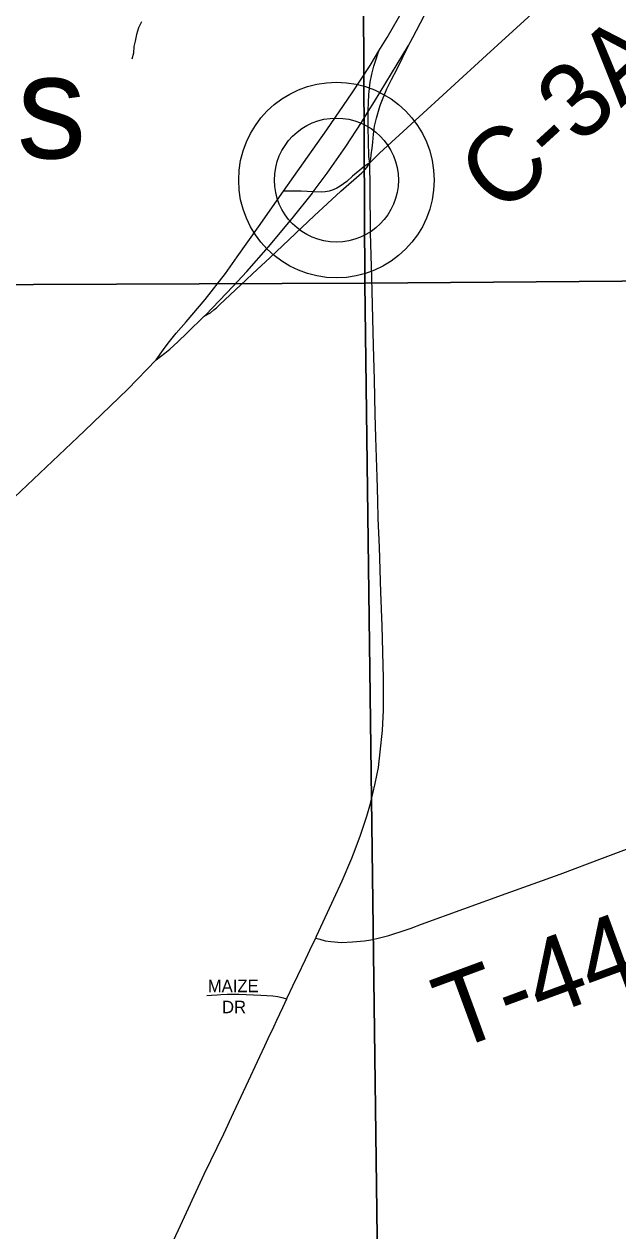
# Model space of a CAD drawing. Extents: x 1985906 to 2360102, y 891258 to 1222054.
# Drawn here: x 2113154 to 2115541, y 1005610 to 1010455 of the extents above; entities that cross this region are included whole.
import ezdxf

# ---------------------------------------------------------------- set-up
doc = ezdxf.new("R2010")
doc.units = 0
for name, color, linetype in [('GM_X_County_Road', 7, 'Continuous'), ('GM_X_County_Road_Text', 7, 'Continuous'), ('GM_X_Interchange_Ramps', 7, 'Continuous'), ('GM_X_Minor_River', 7, 'Continuous'), ('GM_X_Section', 7, 'Continuous'), ('GM_X_State_Route', 7, 'Continuous'), ('GM_X_Township_Road', 7, 'Continuous'), ('GM_X_Township_Road_Text', 7, 'Continuous'), ('GM_X_Township_Subdivision', 7, 'Continuous'), ('GM_X_Township_Subdivision_Text', 7, 'Continuous'), ('GM_X_Unincorporated', 7, 'Continuous'), ('GM_X_Unincorporated_Location', 7, 'Continuous'), ('GM_X_Unincorporated_Text', 7, 'Continuous')]:
    doc.layers.add(name, color=color, linetype=linetype)

msp = doc.modelspace()

# ---------------------------------------------------------------- linework, layer by layer
at = {"layer": 'GM_X_County_Road'}
msp.add_lwpolyline([(2114543.7, 1009898.7), (2114582.7, 1009937.4), (2115013.2, 1010331.1), (2115315.3, 1010608.1), (2115472.7, 1010751.8), (2115809.7, 1011062.8), (2115859.7, 1011112.8), (2115925.8, 1011178.1), (2116009.8, 1011269), (2116069.3, 1011335.5), (2116575.6, 1011894.5), (2116873, 1012222.5), (2116943.9, 1012300.3)], dxfattribs=at)
at = {"layer": 'GM_X_Interchange_Ramps'}
for points in [[(2113878.4, 1009282.4), (2113902.9, 1009296.1), (2113916.9, 1009307.5), (2113927.2, 1009316), (2113939.9, 1009327.8), (2114046.9, 1009428.3), (2114071.5, 1009453.2), (2114143.3, 1009518.7), (2114320.5, 1009685.1), (2114427.3, 1009784.6), (2114511.8, 1009858.8), (2114523.8, 1009870), (2114531.5, 1009880.1), (2114543.7, 1009898.7)], [(2114543.7, 1009898.7), (2114520.6, 1009883.3), (2114503, 1009868.6), (2114474.5, 1009845.3), (2114450.7, 1009823.7), (2114438.2, 1009813.5), (2114424.8, 1009804.4), (2114410.6, 1009796.7), (2114395.8, 1009790.2), (2114380.4, 1009785.2), (2114364.6, 1009782.1), (2114348.5, 1009780.9), (2114316.1, 1009781.8), (2114267.7, 1009784.5), (2114234.6, 1009785), (2114196.6, 1009784.1)]]:
    msp.add_lwpolyline(points, dxfattribs=at)
at = {"layer": 'GM_X_Minor_River'}
msp.add_lwpolyline([(2113625.7, 1010464.1), (2113614, 1010439.8), (2113606.3, 1010413.7), (2113600.6, 1010387.5), (2113594.8, 1010365.4), (2113593.2, 1010339.3), (2113587.5, 1010315.1)], dxfattribs=at)
at = {"layer": 'GM_X_Section'}
for points in [[(2108555.1, 1014727), (2114498.3, 1014780.1), (2114523.8, 1009415.2), (2108532.4, 1009391.8), (2108531.5, 1009537.9)], [(2114498.3, 1014780.1), (2119789.7, 1014747.1), (2119862.8, 1009456.5), (2114523.8, 1009415.2)], [(2119862.8, 1009456.5), (2119854.2, 1004093.4), (2114593.4, 1004032.5), (2114523.8, 1009415.2)], [(2108532.4, 1009391.8), (2114523.8, 1009415.2), (2114593.4, 1004032.5), (2108514.3, 1003954.6), (2108515.8, 1004356.8)]]:
    msp.add_lwpolyline(points, close=True, dxfattribs=at)
at = {"layer": 'GM_X_State_Route'}
for points in [[(2114537.7, 1010104.9), (2114561.9, 1010144), (2114699.2, 1010370), (2114716.2, 1010402.2), (2114762.2, 1010489), (2114812.3, 1010594.2), (2114865.6, 1010706.1), (2114895.1, 1010773.8), (2114925, 1010842.2), (2114993.3, 1011021.3), (2115075.9, 1011235.7), (2115136.6, 1011394.6), (2115227.8, 1011619.5), (2115240.5, 1011650.9), (2115352.5, 1011942.7), (2115537, 1012416.4), (2115632.1, 1012660.9), (2115658.3, 1012729.2), (2115688.7, 1012808.2), (2115723.1, 1012897.5), (2115734, 1012926)], [(2113685.4, 1009107.2), (2113714.8, 1009149.5), (2113733, 1009174.7), (2113766, 1009214.6), (2113806, 1009260.6), (2113882.4, 1009350.2), (2113963.4, 1009453.8), (2114011, 1009520.7), (2114096.6, 1009641.1), (2114196.6, 1009784.1), (2114237.7, 1009842.9), (2114370.4, 1010030.7), (2114472.8, 1010179.5), (2114544.8, 1010289.5), (2114580.4, 1010347.7), (2114613.4, 1010401.7), (2114679.5, 1010515.3)], [(2114543.7, 1009898.7), (2114540.8, 1009912.6), (2114539.2, 1009925), (2114536.9, 1010042.6), (2114537.7, 1010104.9), (2114537.7, 1010108.3), (2114540.2, 1010173.3), (2114545.5, 1010222.3), (2114551.4, 1010254.8), (2114560, 1010286.6), (2114565.3, 1010302.3), (2114580.4, 1010347.7)], [(2114543.7, 1009898.7), (2114548.2, 1009914.8), (2114549.6, 1009930), (2114553.3, 1009957.7), (2114555.2, 1009980.9), (2114558.1, 1010013.5), (2114563.1, 1010045.9), (2114570, 1010077.9), (2114584.3, 1010124.9), (2114586.9, 1010132.2), (2114612.2, 1010195.6), (2114630.9, 1010233.2), (2114653, 1010276), (2114699.2, 1010370)], [(2113685.4, 1009107.2), (2113720, 1009134.7), (2113740, 1009150.3), (2113771.7, 1009179.4), (2113809, 1009215.6), (2113878.4, 1009282.4), (2113884.6, 1009288.4), (2113993.7, 1009402.3), (2114049.8, 1009462.2), (2114136.5, 1009560.9), (2114231.2, 1009674.4), (2114313, 1009777.1), (2114316.1, 1009781.8), (2114371.6, 1009856.4), (2114446.7, 1009964.3), (2114509.8, 1010060.3), (2114537.7, 1010104.9)], [(2114170, 1006455.9), (2114194, 1006507.6), (2114210.2, 1006541.8), (2114212, 1006545.5), (2114234.7, 1006593.6), (2114254.8, 1006636.1), (2114285.1, 1006700), (2114312.5, 1006757.5), (2114326.1, 1006785.9), (2114329.5, 1006793), (2114356.3, 1006851), (2114399, 1006943), (2114432, 1007016), (2114471.1, 1007106.3), (2114484.5, 1007141.2), (2114506.7, 1007199.2), (2114531.9, 1007275.6), (2114546.7, 1007325.9), (2114565.8, 1007406.7), (2114578, 1007470.9), (2114585.8, 1007533.5), (2114594.5, 1007618.6), (2114598, 1007701), (2114598, 1007829.5), (2114592.9, 1008038.8), (2114588.6, 1008174.2), (2114582.5, 1008354.8), (2114577, 1008470.1), (2114576.4, 1008542.4), (2114573, 1008637.9), (2114571.8, 1008675.4), (2114567.9, 1008795.1), (2114564.8, 1008889.7), (2114562.7, 1009026.9), (2114558.3, 1009165), (2114551.6, 1009436.8), (2114546.8, 1009617.4), (2114544.7, 1009798), (2114543.7, 1009898.7)], [(2113011.8, 1008459.4), (2113369.8, 1008796.9), (2113396.6, 1008822.6), (2113570.6, 1008990.2), (2113685.4, 1009107.2)], [(2113995.5, 1006083.8), (2114046.3, 1006193.1), (2114102, 1006310.4), (2114122, 1006353.5), (2114134.6, 1006382.4), (2114157.5, 1006429.1), (2114170, 1006455.9)], [(2113544.4, 1005124.4), (2113774.4, 1005614.2), (2113878.2, 1005837.2), (2113956.4, 1005999.7), (2113995.5, 1006083.8)]]:
    msp.add_lwpolyline(points, dxfattribs=at)
at = {"layer": 'GM_X_Township_Road'}
msp.add_lwpolyline([(2114326.1, 1006785.9), (2114342.2, 1006781.4), (2114363.9, 1006775.3), (2114386.5, 1006771.8), (2114429.9, 1006768.3), (2114474.2, 1006770), (2114522.8, 1006775.3), (2114547.1, 1006778.7), (2114571.2, 1006784.3), (2114599.2, 1006790.8), (2114619.9, 1006796.7), (2114644.7, 1006803.8), (2114666.1, 1006810.8), (2114709.5, 1006825.5), (2114751.7, 1006841), (2115092.1, 1006964.5), (2115308.7, 1007042.7), (2115478.2, 1007106.6), (2115678.6, 1007181.1), (2115786.9, 1007220), (2115926, 1007271), (2116095.7, 1007333.7), (2116188.1, 1007368.6), (2116316.3, 1007422.6)], dxfattribs=at)
at = {"layer": 'GM_X_Township_Subdivision'}
msp.add_lwpolyline([(2113888.2, 1006554.6), (2113907, 1006556.1), (2113929.8, 1006557.8), (2113945.4, 1006559.4), (2113970.6, 1006560.2), (2113992.3, 1006560.1), (2114017.5, 1006559.9), (2114105.3, 1006556.6), (2114153.3, 1006553.7), (2114173.8, 1006550.9), (2114190.2, 1006546.8), (2114210.2, 1006541.8)], dxfattribs=at)
at = {"layer": 'GM_X_Unincorporated'}
for radius in [392.8, 249]:
    msp.add_circle((2114409.4, 1009829.2), radius, dxfattribs=at)
at = {"layer": 'GM_X_Unincorporated_Location'}
msp.add_line((2114409.4, 1009829.2), (2114409.4, 1009829.2), dxfattribs=at)

# ---------------------------------------------------------------- texts
at = {"layer": 'GM_X_County_Road_Text'}
msp.add_text('C-3A', height=300, rotation=42.3778, dxfattribs=at).set_placement((2115074.9, 1009680.9))
at = {"layer": 'GM_X_Township_Road_Text'}
msp.add_text('T-446', height=300, rotation=20.1972, dxfattribs=at).set_placement((2114877.1, 1006330.5))
at = {"layer": 'GM_X_Township_Subdivision_Text'}
for s, p in [('MAIZE', (2113892.5, 1006568.5)), ('DR', (2113949.7, 1006484.1))]:
    msp.add_text(s, height=50, rotation=0, dxfattribs=at).set_placement(p)
at = {"layer": 'GM_X_Unincorporated_Text'}
msp.add_text('Burnetts Corners', height=417, rotation=0, dxfattribs=at).set_placement((2109188.9, 1009916.7))

doc.saveas('drawing.dxf')
